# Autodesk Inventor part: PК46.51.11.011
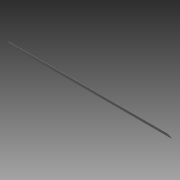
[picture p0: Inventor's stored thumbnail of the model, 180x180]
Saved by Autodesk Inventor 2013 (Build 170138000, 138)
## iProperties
Shininess: 64.0
Length Units: 11269
Angle Units: 11279
Time Units: 11290
Mass Units: 11283
Length Display Precision: 3
Angle Display Precision: 2
Compacted: True
Part Number: PК46.51.11.011
Document SubType Name: Листовой материал
Created: 2004-12
Material: Steel, Mild
Designer: =<Author>
Manufacturer: Standard
Standards Organization: Custom
Description: strip seal
Density: 7.86 g/cm^3
Sheet Metal Rule: По умолчанию
Mass: 246.058 g
Surface Area: 355.595 cm^2
Volume: 31.3051 cm^3
Density: 0.0
Volumn: 0.0
Area: 0.0
PropertySet Name: Model Information
Control State: 0
Master: False
Checked Out: False
Checked Out Date: 2008-10-15
Last Check In Date: 2008-10-15
Author: PVitaliy
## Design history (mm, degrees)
node "ФлнОтгиб1"
feature "Вырез1" dims "d10" = 2 (= Толщина), "d11" = 0
feature "Вырез2" dims "d14" = 2 (= Толщина), "d15" = 0
body "Solid1"
sketch "Эскиз1"
  geometry: L1 (0, 0)-(1062, 0)
  constraints: 2 end point, 1 horizontal, 1 other
  dimensions: "d0" = 1062 distance of L1.start L1.end
feature "Пластина1" dims "d2" = 15, "d3" = 2 (= Ширина_просечки), "d5" = 4 (= Минимальный_остаток), "d7" = 2 (= Радиус_гибки), "d8" = 2, "Толщина" = 2
feature "Изгиб1" dims "d3" = 2 (= Ширина_просечки), "d4" = 1 (= Глубина_просечки), "d5" = 4 (= Минимальный_остаток), "d6" = 2 (= Радиус_гибки), "d7" = 2 (= Радиус_гибки), "d8" = 2, "Толщина" = 2, "Зазор_стыка" = 0.01
sketch "Эскиз2"
  geometry: L1 (1062, 15)-(0, 15) reference; L2 (1062, 0)-(1062, 15) reference; L3 (1062, 0)-(1059.355, 15); L4 (0, 0)-(0, 15) reference; L5 (1062, 0)-(0, 0) reference; L6 (0, 15)-(2.645, 0)
  constraints: 4 end point, 2 point on line
  dimensions: "d9" = 10 deg angle of L3 L2; "d12" = 10 deg angle of L4 L6
sketch "Эскиз3"
  geometry: L1 (1059.355, 0)-(1056.71, 15) reference; L2 (1056.71, 15)-(-2.645, 15) reference; L3 (1059.355, 0)-(0, 0) reference; A1 r 45 centre (1018.951, -30) between (1052.492, 0) and (1018.951, 15)
  constraints: 2 point on circle, 2 point on line, 2 tangent, 1 centre point
  dimensions: "d13" = 90 diameter of A1
other parameters: "Радиус_гибки" = 2 (= Толщина), "Ширина_просечки" = 2 (= Толщина), "Глубина_просечки" = 1 (= 0.5 x Толщина), "Размер_высечки" = 8 (= 4 x Толщина), "Минимальный_остаток" = 4 (= 2 x Толщина), "Радиус_перехода" = 2 (= Радиус_гибки), "JacobiRadiusSize" = 2 (= Толщина), "GapSize" = 2 (= Толщина)
